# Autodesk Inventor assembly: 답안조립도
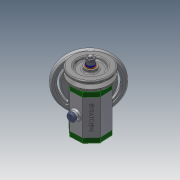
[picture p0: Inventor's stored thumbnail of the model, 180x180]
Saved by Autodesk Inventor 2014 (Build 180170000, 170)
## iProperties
Created: 2017-06
Part Number: 답안조립도
Document SubType Name: Assembly
Designer: Administrator
Author: Administrator
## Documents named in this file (14)
- C:\Users\Administrator\Desktop\470607V1015\답안조립도.iam
- C:\Users\Administrator\Desktop\470607V1015\본체1.ipt
- C:\Users\Administrator\Desktop\470607V1015\축.ipt
- C:\Users\Administrator\Desktop\470607V1015\베어링 15 x 32 x 9.ipt
- C:\Users\Administrator\Desktop\470607V1015\V벨트풀리.ipt
- C:\Users\Administrator\Desktop\470607V1015\키 3 x 3 x 12.ipt
- C:\Users\Administrator\Desktop\470607V1015\뒤커버.ipt
- C:\Users\Administrator\Desktop\470607V1015\앞커버.ipt
- C:\Users\Administrator\Desktop\470607V1015\오일 실 15 25 7.ipt
- C:\Users\Administrator\Desktop\470607V1015\고무캡.ipt
- C:\Users\Administrator\Desktop\470607V1015\볼트 M4 x 12.ipt
- C:\Users\Administrator\Desktop\470607V1015\너트 M 8.ipt
- C:\Users\Administrator\Desktop\470607V1015\스프링와셔 8.ipt
- C:\Users\Administrator\Desktop\470607V1015\와셔 8x17.ipt
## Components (2 placed, 2 different names)
1. V벨트풀리:1 — 각도:2
2. 고무캡:1
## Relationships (1: Angle 1)
- 각도:2 [Angle]: V벨트풀리:1
